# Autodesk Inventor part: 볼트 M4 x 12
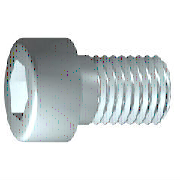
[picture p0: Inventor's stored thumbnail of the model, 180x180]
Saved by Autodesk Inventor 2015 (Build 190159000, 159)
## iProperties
IsCustomPart: 0
Created: 2012-02
Part Number: 볼트 M4 x 12
Material: 스테인리스강
Description: 6각 소켓 머리 캡 나사
Document SubType Name: Modeling
Standard: ISO 4762
Designer: mduedu
Standard Revision: Fourth edition 2004-03-01
Standards Organization: ISO
Language: ko-KR
Size Designation: M4 x 12
Categories: <MemberInstance><Categories><Category DisplayName="조임쇠" InternalName="e4da775c-781d-43d5-af7c-5136215cf5a6" Mnemonic="FSTN"><Category DisplayName="볼트" InternalN
Density: 8.08 g/cm^3
Mass: 2.29719 g
Surface Area: 3.30853 cm^2
Volume: 0.284306 cm^3
Appearance: 반광택
Author: mduedu
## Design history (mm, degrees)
sketch "스케치1"
  geometry: L1 (-1, 0)-(12, 0); L2 (12, 0)-(12, 2); L3 (12, 2)-(1.75, 2); L4 (1.75, 2)-(1.32, 2); L5 (1.32, 2)-(0, 2); L6 (0, 2)-(0, 3.5); L7 (0, 3.5)-(-4, 3.5); L8 (-4, 3.5)-(-4, 1.732); L9 (-4, 1.732)-(-2, 1.732); L10 (-2, 1.732)-(-1, 0); L11 (-7.2, 0)-(15.2, 0) reference; L12 (0, -0.7)-(0, 4.2) reference; L13 (1.75, 2)-(0, 2)
  constraints: 22 end point, 6 parallel, 2 collinear, 2 perpendicular, 1 horizontal, 1 point on line
  dimensions: "d1" = 10.25 distance from line of L3.end L2 (= GEL); "d2" = 0.42952 distance of L4.end L3.end (computed from GAL); "d3" = 4 distance between parallel lines of L8 L6 (= KOH); "d4" = 2 distance of L8.end L9.end (= INTI); "d5" = 60 deg angle of L10 L1; "d6" = 4 diameter of L3 L1 (= GD); "d7" = 4 diameter of L5 L1 (= BDM); "d8" = 3.4641 diameter of L9 L1 (= 1.1547 x SW); "d9" = 7 diameter of L7 L1 (= KOD); "d26" = 12 distance between parallel lines of L12 L2 (= NLG)
revolve "본체" sketch "스케치1" stored, may be unused: angle "d10" = 90 deg
sketch "스케치2"
  geometry: L1 (0, -4.9)-(0, 4.9) reference; L2 (-4.9, 0)-(4.9, 0) reference; L3 (1.732, 0)-(0.866, -1.5); L4 (0.866, -1.5)-(-0.866, -1.5); L5 (-0.866, -1.5)-(-1.732, 0); L6 (-1.732, 0)-(-0.866, 1.5); L7 (-0.866, 1.5)-(0.866, 1.5); L8 (0.866, 1.5)-(1.732, 0); 2 further points
  constraints: 12 end point, 1 coincident, 1 horizontal alignment, 1 point on line, 12 other
extrude "슬롯" join sketch "스케치2" stored distance "d11" = 10; taper "d12" = 0 deg
workplane "Work Plane1"
fillet "Fillet2" dims "d30" = 0.1 (= R)
body "Solid1"
fillet "모깎기1" dims "d17" = 0.4 (= RR)
feature "스레드" dims "d13" = 10.25 (= GEL), "d14" = 0
chamfer "모따기1" distance "d15" = 0.42941 (= -0.5 x SPD + 0.5 x GD); stored, may be unused: second distance "d16" = 0.42941 (= GUL), angle "d27" = 45 deg
other parameters: "GD" = 4 [user parameter; used in 2 equation terms], "NLG" = 12 [user parameter; used in 1 equation term], "GEL" = 10.25 [user parameter; used in 2 equation terms], "KOD" = 7 [user parameter; used in 1 equation term], "KOH" = 4 [user parameter; used in 1 equation term], "INTI" = 2 [user parameter; used in 1 equation term], "GAL" = 0.42941 (= 0.61345 x PTC) [user parameter; used in 1 equation term], "GUL" = 0.42941 (= 0.61345 x PTC) [user parameter; used in 1 equation term], "BDM" = 4 (= NND) [user parameter; used in 1 equation term], "SW" = 3 [user parameter; used in 2 equation terms], "RR" = 0.4 [user parameter; used in 1 equation term], "SPD" = 3.14117 (= NND - 1.2269 x PTC) [user parameter; used in 1 equation term], "d19" = 0, "d28" = 0, "d29" = 0, "R" = 0.1 [user parameter; used in 1 equation term], "TOA" = 30 deg [user parameter], "GD1" = 3.14117 (= THREADDIA - 1.2269 x PTC) [user parameter], "THREADDIA" = 4 [user parameter; used in 1 equation term], "FAWI" = 45 deg [user parameter], "TPU" = 14.28571 (computed from PTC) [user parameter], "PTC" = 0.7 [user parameter; used in 5 equation terms], "NND" = 4 [user parameter; used in 2 equation terms], "E0" = 3.465 (= 1.155 x SW) [user parameter]
